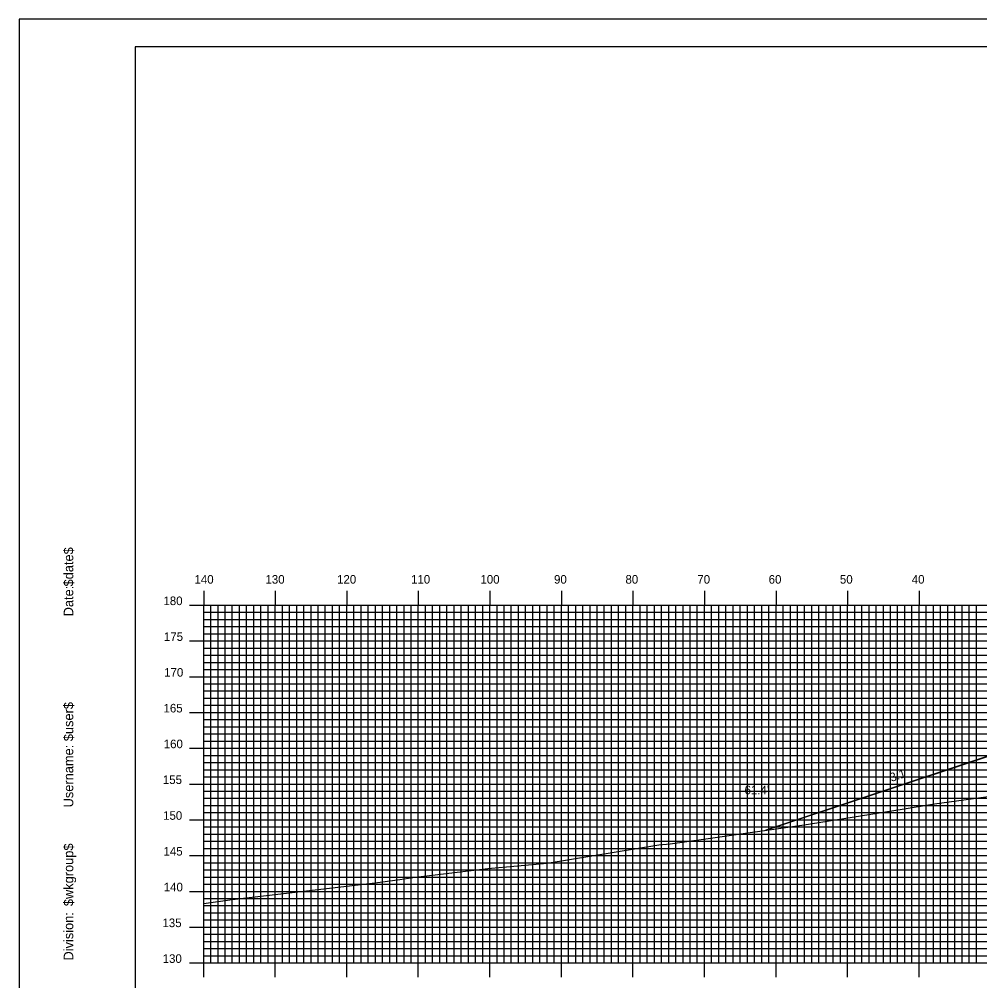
# Model space of a CAD drawing. Extents: x 1793272 to 1793615, y 442591 to 442811.
# Drawn here: x 1793272 to 1793406.3, y 442676.2 to 442810.5 of the extents above; entities that cross this region are included whole.
import ezdxf

# ---------------------------------------------------------------- set-up
doc = ezdxf.new("R2010")
doc.units = 0
for name, color, linetype in [('ANNOTATION', 7, 'Continuous'), ('BORDER', 7, 'Continuous'), ('D_Roadway_Centerline', 7, 'Continuous'), ('D_Roadway_SlopeLines', 7, 'Continuous'), ('D_Text_Standard', 7, 'Continuous'), ('H_V ANNOTATION', 7, 'Continuous'), ('MAJOR', 7, 'Continuous'), ('MINOR', 7, 'Continuous'), ('PLOT BOUNDARY', 7, 'Continuous'), ('S_Roadway_Centerline', 7, 'Continuous')]:
    doc.layers.add(name, color=color, linetype=linetype)

msp = doc.modelspace()

# ---------------------------------------------------------------- linework, layer by layer
at = {"layer": 'BORDER'}
msp.add_lwpolyline([(1793288.2, 442596.67), (1793608.2, 442596.67), (1793608.2, 442806.67), (1793288.2, 442806.67)], close=True, dxfattribs=at)
at = {"layer": 'D_Roadway_Centerline'}
msp.add_lwpolyline([(1793376.38, 442697.2), (1793407.52, 442707.58), (1793414.8, 442710.01), (1793417.8, 442710.13), (1793425.8, 442710.45), (1793437.8, 442710.21), (1793449.8, 442709.97), (1793457.8, 442709.65), (1793467.97, 442707.1), (1793472.24, 442705.67)], dxfattribs=at)
at = {"layer": 'D_Roadway_SlopeLines'}
msp.add_lwpolyline([(1793414.8, 442710.01), (1793376.38, 442697.2)], dxfattribs=at)
at = {"layer": 'MAJOR'}
for p, q in [((1793297.8, 442730.67), (1793297.8, 442728.67)), ((1793307.8, 442730.67), (1793307.8, 442728.67)), ((1793317.8, 442730.67), (1793317.8, 442728.67)), ((1793327.8, 442730.67), (1793327.8, 442728.67)), ((1793337.8, 442730.67), (1793337.8, 442728.67)), ((1793347.8, 442730.67), (1793347.8, 442728.67)), ((1793357.8, 442730.67), (1793357.8, 442728.67)), ((1793367.8, 442730.67), (1793367.8, 442728.67)), ((1793377.8, 442730.67), (1793377.8, 442728.67)), ((1793387.8, 442730.67), (1793387.8, 442728.67)), ((1793397.8, 442730.67), (1793397.8, 442728.67)), ((1793295.8, 442728.67), (1793297.8, 442728.67)), ((1793297.8, 442728.67), (1793577.8, 442728.67)), ((1793297.8, 442678.67), (1793297.8, 442728.67)), ((1793297.8, 442678.67), (1793297.8, 442728.67)), ((1793297.8, 442728.67), (1793577.8, 442728.67)), ((1793307.8, 442678.67), (1793307.8, 442728.67)), ((1793317.8, 442678.67), (1793317.8, 442728.67)), ((1793327.8, 442678.67), (1793327.8, 442728.67)), ((1793337.8, 442678.67), (1793337.8, 442728.67)), ((1793347.8, 442678.67), (1793347.8, 442728.67)), ((1793357.8, 442678.67), (1793357.8, 442728.67)), ((1793367.8, 442678.67), (1793367.8, 442728.67)), ((1793377.8, 442678.67), (1793377.8, 442728.67)), ((1793387.8, 442678.67), (1793387.8, 442728.67)), ((1793397.8, 442678.67), (1793397.8, 442728.67)), ((1793295.8, 442723.67), (1793297.8, 442723.67)), ((1793297.8, 442723.67), (1793577.8, 442723.67)), ((1793295.8, 442718.67), (1793297.8, 442718.67)), ((1793297.8, 442718.67), (1793577.8, 442718.67)), ((1793295.8, 442713.67), (1793297.8, 442713.67)), ((1793297.8, 442713.67), (1793577.8, 442713.67)), ((1793295.8, 442708.67), (1793297.8, 442708.67)), ((1793297.8, 442708.67), (1793577.8, 442708.67)), ((1793295.8, 442703.67), (1793297.8, 442703.67)), ((1793297.8, 442703.67), (1793577.8, 442703.67)), ((1793295.8, 442698.67), (1793297.8, 442698.67)), ((1793297.8, 442698.67), (1793577.8, 442698.67)), ((1793295.8, 442693.67), (1793297.8, 442693.67)), ((1793297.8, 442693.67), (1793577.8, 442693.67)), ((1793295.8, 442688.67), (1793297.8, 442688.67)), ((1793297.8, 442688.67), (1793577.8, 442688.67)), ((1793295.8, 442683.67), (1793297.8, 442683.67)), ((1793297.8, 442683.67), (1793577.8, 442683.67)), ((1793295.8, 442678.67), (1793297.8, 442678.67)), ((1793297.8, 442678.67), (1793577.8, 442678.67)), ((1793297.8, 442678.67), (1793577.8, 442678.67)), ((1793297.8, 442676.66), (1793297.8, 442678.67)), ((1793307.8, 442676.66), (1793307.8, 442678.67)), ((1793317.8, 442676.66), (1793317.8, 442678.67)), ((1793327.8, 442676.66), (1793327.8, 442678.67)), ((1793337.8, 442676.66), (1793337.8, 442678.67)), ((1793347.8, 442676.66), (1793347.8, 442678.67)), ((1793357.8, 442676.66), (1793357.8, 442678.67)), ((1793367.8, 442676.66), (1793367.8, 442678.67)), ((1793377.8, 442676.66), (1793377.8, 442678.67)), ((1793387.8, 442676.66), (1793387.8, 442678.67)), ((1793397.8, 442676.66), (1793397.8, 442678.67))]:
    msp.add_line(p, q, dxfattribs=at)
at = {"layer": 'MINOR'}
for p, q in [((1793298.8, 442678.67), (1793298.8, 442728.67)), ((1793299.8, 442678.67), (1793299.8, 442728.67)), ((1793300.8, 442678.67), (1793300.8, 442728.67)), ((1793301.8, 442678.67), (1793301.8, 442728.67)), ((1793302.8, 442678.67), (1793302.8, 442728.67)), ((1793303.8, 442678.67), (1793303.8, 442728.67)), ((1793304.8, 442678.67), (1793304.8, 442728.67)), ((1793305.8, 442678.67), (1793305.8, 442728.67)), ((1793306.8, 442678.67), (1793306.8, 442728.67)), ((1793308.8, 442678.67), (1793308.8, 442728.67)), ((1793309.8, 442678.67), (1793309.8, 442728.67)), ((1793310.8, 442678.67), (1793310.8, 442728.67)), ((1793311.8, 442678.67), (1793311.8, 442728.67)), ((1793312.8, 442678.67), (1793312.8, 442728.67)), ((1793313.8, 442678.67), (1793313.8, 442728.67)), ((1793314.8, 442678.67), (1793314.8, 442728.67)), ((1793315.8, 442678.67), (1793315.8, 442728.67)), ((1793316.8, 442678.67), (1793316.8, 442728.67)), ((1793318.8, 442678.67), (1793318.8, 442728.67)), ((1793319.8, 442678.67), (1793319.8, 442728.67)), ((1793320.8, 442678.67), (1793320.8, 442728.67)), ((1793321.8, 442678.67), (1793321.8, 442728.67)), ((1793322.8, 442678.67), (1793322.8, 442728.67)), ((1793323.8, 442678.67), (1793323.8, 442728.67)), ((1793324.8, 442678.67), (1793324.8, 442728.67)), ((1793325.8, 442678.67), (1793325.8, 442728.67)), ((1793326.8, 442678.67), (1793326.8, 442728.67)), ((1793328.8, 442678.67), (1793328.8, 442728.67)), ((1793329.8, 442678.67), (1793329.8, 442728.67)), ((1793330.8, 442678.67), (1793330.8, 442728.67)), ((1793331.8, 442678.67), (1793331.8, 442728.67)), ((1793332.8, 442678.67), (1793332.8, 442728.67)), ((1793333.8, 442678.67), (1793333.8, 442728.67)), ((1793334.8, 442678.67), (1793334.8, 442728.67)), ((1793335.8, 442678.67), (1793335.8, 442728.67)), ((1793336.8, 442678.67), (1793336.8, 442728.67)), ((1793338.8, 442678.67), (1793338.8, 442728.67)), ((1793339.8, 442678.67), (1793339.8, 442728.67)), ((1793340.8, 442678.67), (1793340.8, 442728.67)), ((1793341.8, 442678.67), (1793341.8, 442728.67)), ((1793342.8, 442678.67), (1793342.8, 442728.67)), ((1793343.8, 442678.67), (1793343.8, 442728.67)), ((1793344.8, 442678.67), (1793344.8, 442728.67)), ((1793345.8, 442678.67), (1793345.8, 442728.67)), ((1793346.8, 442678.67), (1793346.8, 442728.67)), ((1793348.8, 442678.67), (1793348.8, 442728.67)), ((1793349.8, 442678.67), (1793349.8, 442728.67)), ((1793350.8, 442678.67), (1793350.8, 442728.67)), ((1793351.8, 442678.67), (1793351.8, 442728.67)), ((1793352.8, 442678.67), (1793352.8, 442728.67)), ((1793353.8, 442678.67), (1793353.8, 442728.67)), ((1793354.8, 442678.67), (1793354.8, 442728.67)), ((1793355.8, 442678.67), (1793355.8, 442728.67)), ((1793356.8, 442678.67), (1793356.8, 442728.67)), ((1793358.8, 442678.67), (1793358.8, 442728.67)), ((1793359.8, 442678.67), (1793359.8, 442728.67)), ((1793360.8, 442678.67), (1793360.8, 442728.67)), ((1793361.8, 442678.67), (1793361.8, 442728.67)), ((1793362.8, 442678.67), (1793362.8, 442728.67)), ((1793363.8, 442678.67), (1793363.8, 442728.67)), ((1793364.8, 442678.67), (1793364.8, 442728.67)), ((1793365.8, 442678.67), (1793365.8, 442728.67)), ((1793366.8, 442678.67), (1793366.8, 442728.67)), ((1793368.8, 442678.67), (1793368.8, 442728.67)), ((1793369.8, 442678.67), (1793369.8, 442728.67)), ((1793370.8, 442678.67), (1793370.8, 442728.67)), ((1793371.8, 442678.67), (1793371.8, 442728.67)), ((1793372.8, 442678.67), (1793372.8, 442728.67)), ((1793373.8, 442678.67), (1793373.8, 442728.67)), ((1793374.8, 442678.67), (1793374.8, 442728.67)), ((1793375.8, 442678.67), (1793375.8, 442728.67)), ((1793376.8, 442678.67), (1793376.8, 442728.67)), ((1793378.8, 442678.67), (1793378.8, 442728.67)), ((1793379.8, 442678.67), (1793379.8, 442728.67)), ((1793380.8, 442678.67), (1793380.8, 442728.67)), ((1793381.8, 442678.67), (1793381.8, 442728.67)), ((1793382.8, 442678.67), (1793382.8, 442728.67)), ((1793383.8, 442678.67), (1793383.8, 442728.67)), ((1793384.8, 442678.67), (1793384.8, 442728.67)), ((1793385.8, 442678.67), (1793385.8, 442728.67)), ((1793386.8, 442678.67), (1793386.8, 442728.67)), ((1793388.8, 442678.67), (1793388.8, 442728.67)), ((1793389.8, 442678.67), (1793389.8, 442728.67)), ((1793390.8, 442678.67), (1793390.8, 442728.67)), ((1793391.8, 442678.67), (1793391.8, 442728.67)), ((1793392.8, 442678.67), (1793392.8, 442728.67)), ((1793393.8, 442678.67), (1793393.8, 442728.67)), ((1793394.8, 442678.67), (1793394.8, 442728.67)), ((1793395.8, 442678.67), (1793395.8, 442728.67)), ((1793396.8, 442678.67), (1793396.8, 442728.67)), ((1793398.8, 442678.67), (1793398.8, 442728.67)), ((1793399.8, 442678.67), (1793399.8, 442728.67)), ((1793400.8, 442678.67), (1793400.8, 442728.67)), ((1793401.8, 442678.67), (1793401.8, 442728.67)), ((1793402.8, 442678.67), (1793402.8, 442728.67)), ((1793403.8, 442678.67), (1793403.8, 442728.67)), ((1793404.8, 442678.67), (1793404.8, 442728.67)), ((1793405.8, 442678.67), (1793405.8, 442728.67)), ((1793297.8, 442727.67), (1793577.8, 442727.67)), ((1793297.8, 442727.67), (1793299.8, 442727.67)), ((1793297.8, 442726.67), (1793577.8, 442726.67)), ((1793297.8, 442726.67), (1793299.8, 442726.67)), ((1793297.8, 442725.67), (1793577.8, 442725.67)), ((1793297.8, 442725.67), (1793299.8, 442725.67)), ((1793297.8, 442724.67), (1793577.8, 442724.67)), ((1793297.8, 442724.67), (1793299.8, 442724.67)), ((1793297.8, 442722.67), (1793577.8, 442722.67)), ((1793297.8, 442722.67), (1793299.8, 442722.67)), ((1793297.8, 442721.67), (1793577.8, 442721.67)), ((1793297.8, 442721.67), (1793299.8, 442721.67)), ((1793297.8, 442720.67), (1793577.8, 442720.67)), ((1793297.8, 442720.67), (1793299.8, 442720.67)), ((1793297.8, 442719.67), (1793577.8, 442719.67)), ((1793297.8, 442719.67), (1793299.8, 442719.67)), ((1793297.8, 442717.67), (1793577.8, 442717.67)), ((1793297.8, 442717.67), (1793299.8, 442717.67)), ((1793297.8, 442716.67), (1793577.8, 442716.67)), ((1793297.8, 442716.67), (1793299.8, 442716.67)), ((1793297.8, 442715.67), (1793577.8, 442715.67)), ((1793297.8, 442715.67), (1793299.8, 442715.67)), ((1793297.8, 442714.67), (1793577.8, 442714.67)), ((1793297.8, 442714.67), (1793299.8, 442714.67)), ((1793297.8, 442712.67), (1793577.8, 442712.67)), ((1793297.8, 442712.67), (1793299.8, 442712.67)), ((1793297.8, 442711.67), (1793577.8, 442711.67)), ((1793297.8, 442711.67), (1793299.8, 442711.67)), ((1793297.8, 442710.67), (1793577.8, 442710.67)), ((1793297.8, 442710.67), (1793299.8, 442710.67)), ((1793297.8, 442709.67), (1793577.8, 442709.67)), ((1793297.8, 442709.67), (1793299.8, 442709.67)), ((1793297.8, 442707.67), (1793577.8, 442707.67)), ((1793297.8, 442707.67), (1793299.8, 442707.67)), ((1793297.8, 442706.67), (1793577.8, 442706.67)), ((1793297.8, 442706.67), (1793299.8, 442706.67)), ((1793297.8, 442705.67), (1793577.8, 442705.67)), ((1793297.8, 442705.67), (1793299.8, 442705.67)), ((1793297.8, 442704.67), (1793577.8, 442704.67)), ((1793297.8, 442704.67), (1793299.8, 442704.67)), ((1793297.8, 442702.67), (1793577.8, 442702.67)), ((1793297.8, 442702.67), (1793299.8, 442702.67)), ((1793297.8, 442701.67), (1793577.8, 442701.67)), ((1793297.8, 442701.67), (1793299.8, 442701.67)), ((1793297.8, 442700.67), (1793577.8, 442700.67)), ((1793297.8, 442700.67), (1793299.8, 442700.67)), ((1793297.8, 442699.67), (1793577.8, 442699.67)), ((1793297.8, 442699.67), (1793299.8, 442699.67)), ((1793297.8, 442697.67), (1793577.8, 442697.67)), ((1793297.8, 442697.67), (1793299.8, 442697.67)), ((1793297.8, 442696.67), (1793577.8, 442696.67)), ((1793297.8, 442696.67), (1793299.8, 442696.67)), ((1793297.8, 442695.67), (1793577.8, 442695.67)), ((1793297.8, 442695.67), (1793299.8, 442695.67)), ((1793297.8, 442694.67), (1793577.8, 442694.67)), ((1793297.8, 442694.67), (1793299.8, 442694.67)), ((1793297.8, 442692.67), (1793577.8, 442692.67)), ((1793297.8, 442692.67), (1793299.8, 442692.67)), ((1793297.8, 442691.67), (1793577.8, 442691.67)), ((1793297.8, 442691.67), (1793299.8, 442691.67)), ((1793297.8, 442690.67), (1793577.8, 442690.67)), ((1793297.8, 442690.67), (1793299.8, 442690.67)), ((1793297.8, 442689.67), (1793577.8, 442689.67)), ((1793297.8, 442689.67), (1793299.8, 442689.67)), ((1793297.8, 442687.67), (1793577.8, 442687.67)), ((1793297.8, 442687.67), (1793299.8, 442687.67)), ((1793297.8, 442686.67), (1793577.8, 442686.67)), ((1793297.8, 442686.67), (1793299.8, 442686.67)), ((1793297.8, 442685.67), (1793577.8, 442685.67)), ((1793297.8, 442685.67), (1793299.8, 442685.67)), ((1793297.8, 442684.67), (1793577.8, 442684.67)), ((1793297.8, 442684.67), (1793299.8, 442684.67)), ((1793297.8, 442682.67), (1793577.8, 442682.67)), ((1793297.8, 442682.67), (1793299.8, 442682.67)), ((1793297.8, 442681.67), (1793577.8, 442681.67)), ((1793297.8, 442681.67), (1793299.8, 442681.67)), ((1793297.8, 442680.67), (1793577.8, 442680.67)), ((1793297.8, 442680.67), (1793299.8, 442680.67)), ((1793297.8, 442679.67), (1793577.8, 442679.67)), ((1793297.8, 442679.67), (1793299.8, 442679.67))]:
    msp.add_line(p, q, dxfattribs=at)
at = {"layer": 'PLOT BOUNDARY'}
msp.add_lwpolyline([(1793272.01, 442590.55), (1793612.01, 442590.55), (1793612.01, 442810.55), (1793272.01, 442810.55)], close=True, dxfattribs=at)
at = {"layer": 'S_Roadway_Centerline'}
msp.add_lwpolyline([(1793297.8, 442686.99), (1793301.77, 442687.53), (1793321.78, 442689.87), (1793325.21, 442690.34), (1793327.04, 442690.61), (1793337.5, 442691.86), (1793345.83, 442692.63), (1793361.4, 442695.16), (1793363.02, 442695.32), (1793367.66, 442695.97), (1793381.75, 442697.96), (1793395.43, 442700.17), (1793399.95, 442700.9), (1793410.19, 442702.29)], dxfattribs=at)

# ---------------------------------------------------------------- texts
at = {"layer": 'ANNOTATION'}
msp.add_text('3:1', height=1.2, rotation=18.4349, dxfattribs=at).set_placement((1793393.93, 442703.96))
at = {"layer": 'BORDER'}
for s, p in [('$date$', (1793279.57, 442731.28)), ('Date:', (1793279.57, 442727.1)), ('$user$', (1793279.57, 442709.65)), ('Username:', (1793279.57, 442700.4)), ('$wkgroup$', (1793279.57, 442686.6)), ('Division:', (1793279.57, 442679))]:
    msp.add_text(s, height=1.339, rotation=90, dxfattribs=at).set_placement(p)
at = {"layer": 'D_Text_Standard'}
msp.add_text("61.4'", height=1.2, dxfattribs=at).set_placement((1793373.4, 442702.24))
at = {"layer": 'H_V ANNOTATION'}
for s, p in [('140', (1793296.51, 442731.67)), ('130', (1793306.43, 442731.67)), ('120', (1793316.44, 442731.67)), ('110', (1793326.78, 442731.67)), ('100', (1793336.48, 442731.67)), ('90', (1793346.77, 442731.67)), ('80', (1793356.75, 442731.67)), ('70', (1793366.8, 442731.67)), ('60', (1793376.77, 442731.67)), ('50', (1793386.73, 442731.67)), ('40', (1793396.77, 442731.67)), ('180', (1793292.17, 442728.67)), ('175', (1793292.24, 442723.67)), ('170', (1793292.27, 442718.67)), ('165', (1793292.18, 442713.67)), ('160', (1793292.21, 442708.67)), ('155', (1793292.09, 442703.67)), ('150', (1793292.12, 442698.67)), ('145', (1793292.18, 442693.67)), ('140', (1793292.21, 442688.67)), ('135', (1793292.03, 442683.67)), ('130', (1793292.06, 442678.67))]:
    msp.add_text(s, height=1.2, dxfattribs=at).set_placement(p)
at = {"layer": 'MAJOR'}
msp.add_text('-', height=0.012, dxfattribs=at).set_placement((1793297.79, 442678.67))

doc.saveas('drawing.dxf')
